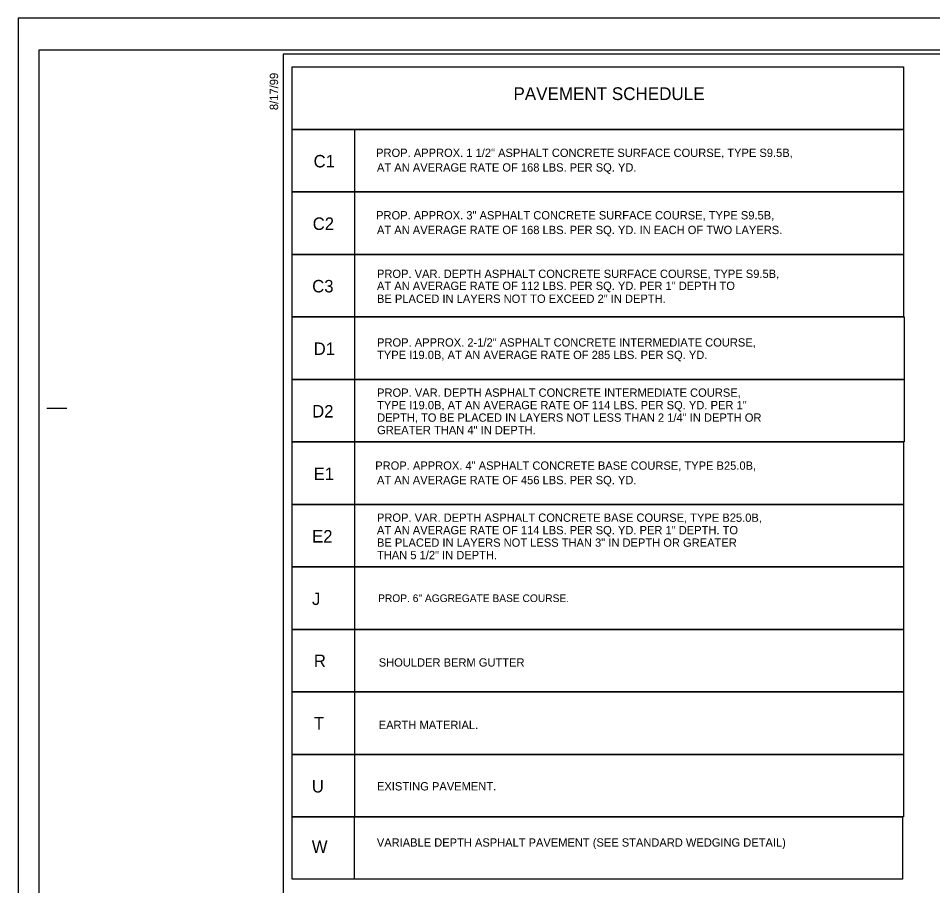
# Model space of a CAD drawing. Extents: x 2532463 to 2534146, y 189689 to 190784.
# Drawn here: x 2532463 to 2533037, y 190239 to 190784 of the extents above; entities that cross this region are included whole.
import ezdxf

# ---------------------------------------------------------------- set-up
doc = ezdxf.new("R2010")
doc.units = 0
for name, color, linetype in [('Old_Level_18', 7, 'Continuous'), ('Old_Level_19', 7, 'Continuous'), ('Old_Level_2', 7, 'Continuous'), ('Old_Level_21', 7, 'Continuous'), ('Old_Level_41', 7, 'Continuous'), ('Old_Level_46', 7, 'Continuous'), ('Old_Level_50', 7, 'Continuous'), ('Old_Level_51', 7, 'Continuous')]:
    doc.layers.add(name, color=color, linetype=linetype)

msp = doc.modelspace()

# ---------------------------------------------------------------- linework, layer by layer
at = {"layer": 'Old_Level_18'}
msp.add_lwpolyline([(2534129.31, 190761.68), (2532629.31, 190761.68), (2532629.31, 189711.68), (2534129.31, 189711.68)], close=True, dxfattribs=at)
at = {"layer": 'Old_Level_19'}
msp.add_lwpolyline([(2532634.89, 190753.64), (2533018.9, 190753.64), (2533018.9, 190714.37), (2532634.89, 190714.37)], close=True, dxfattribs=at)
for points in [[(2532674.16, 190675.09), (2532634.89, 190675.09), (2532634.89, 190714.37), (2533018.89, 190714.37), (2533018.89, 190675.09), (2532674.16, 190675.09), (2532674.16, 190714.37)], [(2532674.16, 190635.82), (2532634.89, 190635.82), (2532634.89, 190675.09), (2533018.89, 190675.09), (2533018.89, 190635.82), (2532674.16, 190635.82), (2532674.16, 190675.09)], [(2532674.16, 190596.55), (2532634.89, 190596.55), (2532634.89, 190635.82), (2533018.89, 190635.82), (2533018.89, 190596.55), (2532674.16, 190596.55), (2532674.16, 190635.82)], [(2532674.21, 190557.23), (2532634.89, 190557.23), (2532634.89, 190596.55), (2533019.37, 190596.55), (2533019.37, 190557.23), (2532674.21, 190557.23), (2532674.21, 190596.55)], [(2532674.21, 190517.91), (2532634.89, 190517.91), (2532634.89, 190557.23), (2533019.38, 190557.23), (2533019.38, 190517.91), (2532674.21, 190517.91), (2532674.21, 190557.23)], [(2532674.16, 190478.64), (2532634.89, 190478.64), (2532634.89, 190517.91), (2533018.89, 190517.91), (2533018.89, 190478.64), (2532674.16, 190478.64), (2532674.16, 190517.91)], [(2532674.16, 190439.36), (2532634.89, 190439.36), (2532634.89, 190478.64), (2533018.89, 190478.64), (2533018.89, 190439.36), (2532674.16, 190439.36), (2532674.16, 190478.64)], [(2532674.16, 190360.82), (2532634.89, 190360.82), (2532634.89, 190400.09), (2533018.89, 190400.09), (2533018.89, 190360.82), (2532674.16, 190360.82), (2532674.16, 190400.09)], [(2532674.16, 190321.55), (2532634.89, 190321.55), (2532634.89, 190360.82), (2533018.89, 190360.82), (2533018.89, 190321.55), (2532674.16, 190321.55), (2532674.16, 190360.82)], [(2532674.16, 190282.28), (2532634.89, 190282.28), (2532634.89, 190321.55), (2533018.89, 190321.55), (2533018.89, 190282.28), (2532674.16, 190282.28), (2532674.16, 190321.55)], [(2532674.1, 190243.07), (2532634.89, 190243.07), (2532634.89, 190282.28), (2533018.3, 190282.28), (2533018.3, 190243.07), (2532674.1, 190243.07), (2532674.1, 190282.28)]]:
    msp.add_lwpolyline(points, dxfattribs=at)
at = {"layer": 'Old_Level_2'}
msp.add_lwpolyline([(2532674.16, 190400.09), (2532634.89, 190400.09), (2532634.89, 190439.36), (2533018.9, 190439.36), (2533018.9, 190400.09), (2532674.16, 190400.09), (2532674.16, 190439.36)], dxfattribs=at)
at = {"layer": 'Old_Level_41'}
msp.add_line((2532480.81, 190539.18), (2532493.31, 190539.18), dxfattribs=at)
at = {"layer": 'Old_Level_46'}
msp.add_line((2532629.31, 190761.68), (2532629.31, 190761.68), dxfattribs=at)
at = {"layer": 'Old_Level_50'}
msp.add_lwpolyline([(2532475.81, 189709.18), (2534141.81, 189709.18), (2534141.81, 190764.18), (2532475.81, 190764.18)], close=True, dxfattribs=at)
at = {"layer": 'Old_Level_51'}
msp.add_lwpolyline([(2532462.81, 189689.18), (2534146.31, 189689.18), (2534146.31, 190784.18), (2532462.81, 190784.18)], close=True, dxfattribs=at)

# ---------------------------------------------------------------- texts
at = {"layer": 'Old_Level_2'}
for s, height, p in [('J ', 7.84, (2532647.37, 190415.45)), ('PROP. 6" AGGREGATE BASE COURSE.', 4.8, (2532688.88, 190417.32))]:
    msp.add_text(s, height=height, dxfattribs=at).set_placement(p)
at = {"layer": 'Old_Level_21'}
for s, height, p in [('PAVEMENT SCHEDULE', 8, (2532773.91, 190732.8)), ('C1', 7.84, (2532648.35, 190690.45)), ('PROP. APPROX. 1 1/2" ASPHALT CONCRETE SURFACE COURSE, TYPE S9.5B,', 5.224, (2532687.62, 190697.04)), ('AT AN AVERAGE RATE OF 168 LBS. PER SQ. YD.', 5.224, (2532688.16, 190687.83)), ('C2', 7.84, (2532647.79, 190651.17)), ('PROP. APPROX. 3" ASPHALT CONCRETE SURFACE COURSE, TYPE S9.5B,', 5.224, (2532687.62, 190657.77)), ('AT AN AVERAGE RATE OF 168 LBS. PER SQ. YD. IN EACH OF TWO LAYERS.', 5.224, (2532688.16, 190648.56)), ('PROP. VAR. DEPTH ASPHALT CONCRETE SURFACE COURSE, TYPE S9.5B,', 5.224, (2532688.16, 190621)), ('C3', 7.84, (2532647.46, 190611.91)), ('AT AN AVERAGE RATE OF 112 LBS. PER SQ. YD. PER 1" DEPTH TO', 5.224, (2532688.16, 190613.44)), ('BE PLACED IN LAYERS NOT TO EXCEED 2" IN DEPTH.', 5.224, (2532688.16, 190605.33)), ('PROP. APPROX. 2-1/2" ASPHALT CONCRETE INTERMEDIATE COURSE,', 5.2305, (2532688.19, 190577.86)), ('D1', 7.85, (2532648.37, 190572.61)), ('TYPE I19.0B, AT AN AVERAGE RATE OF 285 LBS. PER SQ. YD.', 5.2305, (2532688.19, 190570.02)), ('PROP. VAR. DEPTH ASPHALT CONCRETE INTERMEDIATE COURSE,', 5.2305, (2532688.23, 190546.31)), ('TYPE I19.0B, AT AN AVERAGE RATE OF 114 LBS. PER SQ. YD. PER 1" ', 5.2305, (2532688.23, 190538.47)), ('D2', 7.85, (2532647.43, 190533.29)), ('DEPTH, TO BE PLACED IN LAYERS NOT LESS THAN 2 1/4" IN DEPTH OR', 5.2305, (2532688.23, 190530.63)), ('GREATER THAN 4" IN DEPTH.', 5.2305, (2532688.23, 190522.79)), ('PROP. APPROX. 4" ASPHALT CONCRETE BASE COURSE, TYPE B25.0B,', 5.224, (2532687.08, 190500.45)), ('E1', 7.84, (2532648.35, 190493.99)), ('AT AN AVERAGE RATE OF 456 LBS. PER SQ. YD.', 5.224, (2532688.16, 190491.37)), ('PROP. VAR. DEPTH ASPHALT CONCRETE BASE COURSE, TYPE B25.0B,', 5.224, (2532688.16, 190467.73)), ('E2', 7.84, (2532647.41, 190454.72)), ('AT AN AVERAGE RATE OF 114 LBS. PER SQ. YD. PER 1" DEPTH. TO', 5.224, (2532688.16, 190459.9)), ('BE PLACED IN LAYERS NOT LESS THAN 3" IN DEPTH OR GREATER', 5.224, (2532688.16, 190452.07)), ('THAN 5 1/2" IN DEPTH.', 5.224, (2532688.16, 190444.24)), ('R ', 7.84, (2532648.52, 190376.46)), ('SHOULDER BERM GUTTER', 5.224, (2532689.26, 190376.74)), ('T ', 7.84, (2532648.52, 190337.19)), ('EARTH MATERIAL.', 5.224, (2532689.26, 190337.47)), ('U ', 7.84, (2532647.24, 190297.64)), ('EXISTING PAVEMENT.', 5.224, (2532688.16, 190298.92)), ('W ', 7.828, (2532647.22, 190259.67)), ('VARIABLE DEPTH ASPHALT PAVEMENT (SEE STANDARD WEDGING DETAIL)', 5.2158, (2532688.08, 190263.6))]:
    msp.add_text(s, height=height, dxfattribs=at).set_placement(p)
at = {"layer": 'Old_Level_41'}
msp.add_text('8/17/99', height=5.25, rotation=90, dxfattribs=at).set_placement((2532626.06, 190726.48))

doc.saveas('drawing.dxf')
